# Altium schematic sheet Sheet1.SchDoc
size A4; DocumentNumber: 1; SheetNumber: 1; SheetTotal: 2
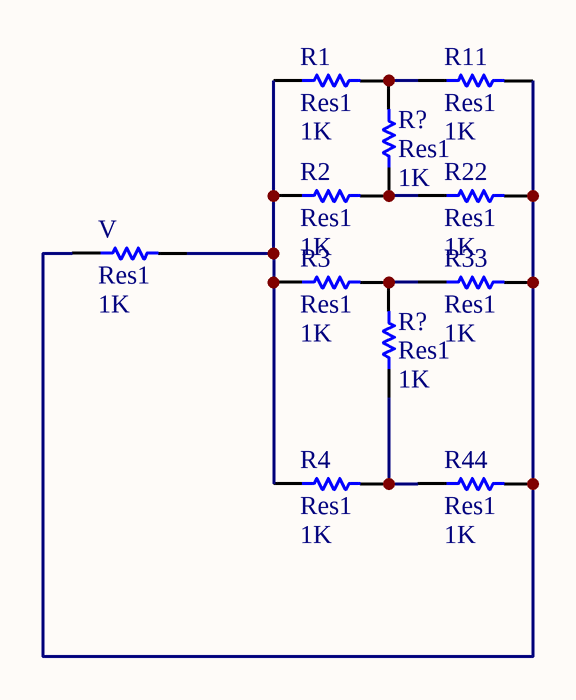
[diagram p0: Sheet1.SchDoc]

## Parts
(Parts that share a designator on the sheet are numbered #1, #2 ... from top to bottom, then left to right.)
R1  Res1  value 1K  [AXIAL-0.3]
R2  Res1  value 1K  [AXIAL-0.3]
R3  Res1  value 1K  [AXIAL-0.3]
R4  Res1  value 1K  [AXIAL-0.3]
R11  Res1  value 1K  [AXIAL-0.3]
R22  Res1  value 1K  [AXIAL-0.3]
R33  Res1  value 1K  [AXIAL-0.3]
R44  Res1  value 1K  [AXIAL-0.3]
R?#1  Res1  value 1K  [AXIAL-0.3]
R?#2  Res1  value 1K  [AXIAL-0.3]
V  Res1  value 1K  [AXIAL-0.3]

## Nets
NetR1_1: R1.1 R2.1 R3.1 R4.1 V.2
NetR1_2: R1.2 R11.1 R?#1.2
NetR2_2: R2.2 R22.1 R?#1.1
NetR3_2: R3.2 R33.1 R?#2.2
NetR4_2: R4.2 R44.1 R?#2.1
NetR11_2: R11.2 R22.2 R33.2 R44.2 V.1

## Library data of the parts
R1-R4 R11 R22 R33 R44 R?#1 R?#2 V = Res1: Resistor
